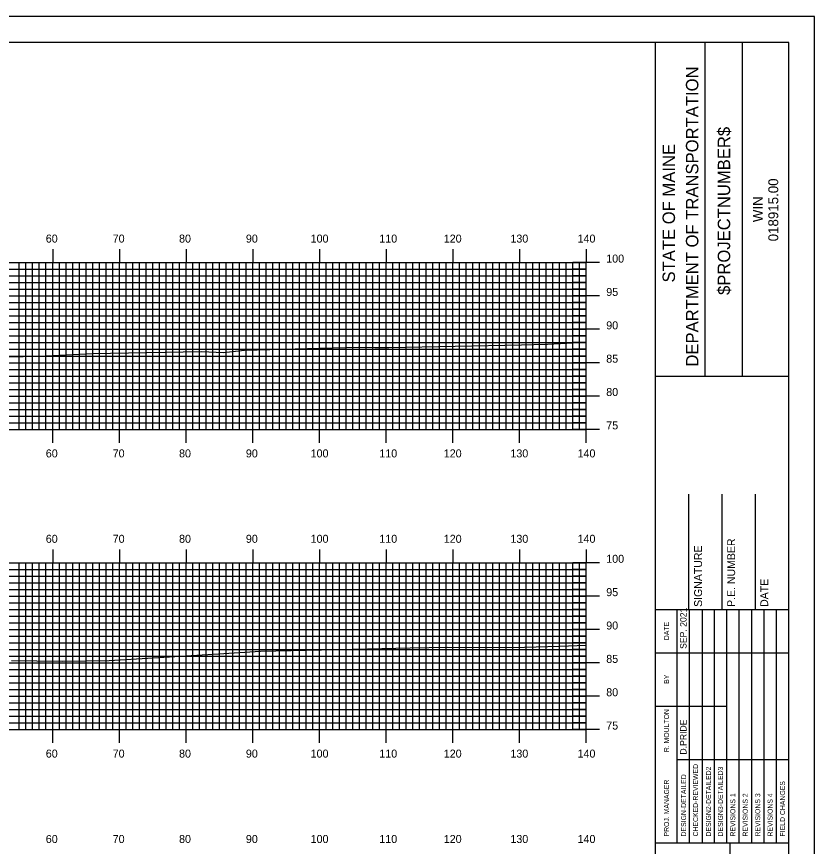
# Model space of a CAD drawing. Extents: x 1777531 to 1777875, y 442591 to 442811.
# Drawn here: x 1777751.9 to 1777871.5, y 442686.2 to 442810.5 of the extents above; entities that cross this region are included whole.
import ezdxf

# ---------------------------------------------------------------- set-up
doc = ezdxf.new("R2010")
doc.units = 0
for name, color, linetype in [('BORDER', 7, 'Continuous'), ('H_V ANNOTATION', 7, 'Continuous'), ('MAJOR', 7, 'Continuous'), ('MINOR', 7, 'Continuous'), ('PLOT BOUNDARY', 7, 'Continuous'), ('S_Roadway_Centerline', 7, 'Continuous')]:
    doc.layers.add(name, color=color, linetype=linetype)

msp = doc.modelspace()

# ---------------------------------------------------------------- linework, layer by layer
at = {"layer": 'BORDER'}
for p, q in [((1777847.68, 442596.67), (1777847.68, 442806.67)), ((1777855.13, 442756.66), (1777855.13, 442806.66)), ((1777860.72, 442756.66), (1777860.72, 442806.66)), ((1777847.68, 442756.65), (1777867.68, 442756.65)), ((1777852.68, 442721.67), (1777852.68, 442738.97)), ((1777857.68, 442721.67), (1777857.68, 442738.97)), ((1777862.68, 442721.67), (1777862.68, 442738.97)), ((1777847.68, 442721.67), (1777867.68, 442721.67)), ((1777847.68, 442686.67), (1777867.68, 442686.67)), ((1777858.86, 442616.67), (1777858.86, 442686.67))]:
    msp.add_line(p, q, dxfattribs=at)
msp.add_lwpolyline([(1777547.68, 442596.67), (1777867.68, 442596.67), (1777867.68, 442806.67), (1777547.68, 442806.67)], close=True, dxfattribs=at)
for points in [[(1777850.91, 442715.17), (1777850.91, 442721.67)], [(1777852.77, 442686.68), (1777852.77, 442721.67)], [(1777854.64, 442721.67), (1777854.64, 442686.68)], [(1777856.5, 442686.68), (1777856.5, 442721.67)], [(1777858.36, 442686.68), (1777858.36, 442721.67)], [(1777860.23, 442686.68), (1777860.23, 442721.67)], [(1777862.09, 442686.68), (1777862.09, 442721.67)], [(1777863.95, 442686.68), (1777863.95, 442721.67)], [(1777865.82, 442686.68), (1777865.82, 442721.67)], [(1777850.91, 442686.68), (1777850.91, 442720.26)], [(1777847.68, 442715.17), (1777867.68, 442715.17)], [(1777847.68, 442707.17), (1777850.91, 442707.17)], [(1777850.91, 442707.17), (1777858.36, 442707.17)], [(1777850.91, 442699.17), (1777867.68, 442699.17)]]:
    msp.add_lwpolyline(points, dxfattribs=at)
at = {"layer": 'MAJOR'}
for p, q in [((1777757.28, 442775.67), (1777757.28, 442773.67)), ((1777767.28, 442775.67), (1777767.28, 442773.67)), ((1777777.28, 442775.67), (1777777.28, 442773.67)), ((1777787.28, 442775.67), (1777787.28, 442773.67)), ((1777797.28, 442775.67), (1777797.28, 442773.67)), ((1777807.28, 442775.67), (1777807.28, 442773.67)), ((1777817.28, 442775.67), (1777817.28, 442773.67)), ((1777827.28, 442775.67), (1777827.28, 442773.67)), ((1777837.28, 442775.67), (1777837.28, 442773.67)), ((1777557.28, 442773.67), (1777837.28, 442773.67)), ((1777557.28, 442773.67), (1777837.28, 442773.67)), ((1777757.28, 442748.67), (1777757.28, 442773.67)), ((1777767.28, 442748.67), (1777767.28, 442773.67)), ((1777777.28, 442748.67), (1777777.28, 442773.67)), ((1777787.28, 442748.67), (1777787.28, 442773.67)), ((1777797.28, 442748.67), (1777797.28, 442773.67)), ((1777807.28, 442748.67), (1777807.28, 442773.67)), ((1777817.28, 442748.67), (1777817.28, 442773.67)), ((1777827.28, 442748.67), (1777827.28, 442773.67)), ((1777839.28, 442773.67), (1777835.27, 442773.67)), ((1777837.28, 442748.67), (1777837.28, 442773.67)), ((1777837.28, 442748.67), (1777837.28, 442773.67)), ((1777557.28, 442768.67), (1777837.28, 442768.67)), ((1777839.28, 442768.67), (1777835.27, 442768.67)), ((1777557.28, 442763.67), (1777837.28, 442763.67)), ((1777839.28, 442763.67), (1777835.27, 442763.67)), ((1777557.28, 442758.67), (1777837.28, 442758.67)), ((1777839.28, 442758.67), (1777835.27, 442758.67)), ((1777557.28, 442753.67), (1777837.28, 442753.67)), ((1777839.28, 442753.67), (1777835.27, 442753.67)), ((1777557.28, 442748.67), (1777837.28, 442748.67)), ((1777557.28, 442748.67), (1777837.28, 442748.67)), ((1777757.28, 442746.66), (1777757.28, 442748.67)), ((1777767.28, 442746.66), (1777767.28, 442748.67)), ((1777777.28, 442746.66), (1777777.28, 442748.67)), ((1777787.28, 442746.66), (1777787.28, 442748.67)), ((1777797.28, 442746.66), (1777797.28, 442748.67)), ((1777807.28, 442746.66), (1777807.28, 442748.67)), ((1777817.28, 442746.66), (1777817.28, 442748.67)), ((1777827.28, 442746.66), (1777827.28, 442748.67)), ((1777839.28, 442748.67), (1777835.27, 442748.67)), ((1777837.28, 442746.66), (1777837.28, 442748.67)), ((1777757.28, 442730.67), (1777757.28, 442728.67)), ((1777767.28, 442730.67), (1777767.28, 442728.67)), ((1777777.28, 442730.67), (1777777.28, 442728.67)), ((1777787.28, 442730.67), (1777787.28, 442728.67)), ((1777797.28, 442730.67), (1777797.28, 442728.67)), ((1777807.28, 442730.67), (1777807.28, 442728.67)), ((1777817.28, 442730.67), (1777817.28, 442728.67)), ((1777827.28, 442730.67), (1777827.28, 442728.67)), ((1777837.28, 442730.67), (1777837.28, 442728.67)), ((1777557.28, 442728.67), (1777837.28, 442728.67)), ((1777557.28, 442728.67), (1777837.28, 442728.67)), ((1777757.28, 442703.67), (1777757.28, 442728.67)), ((1777767.28, 442703.67), (1777767.28, 442728.67)), ((1777777.28, 442703.67), (1777777.28, 442728.67)), ((1777787.28, 442703.67), (1777787.28, 442728.67)), ((1777797.28, 442703.67), (1777797.28, 442728.67)), ((1777807.28, 442703.67), (1777807.28, 442728.67)), ((1777817.28, 442703.67), (1777817.28, 442728.67)), ((1777827.28, 442703.67), (1777827.28, 442728.67)), ((1777839.28, 442728.67), (1777835.27, 442728.67)), ((1777837.28, 442703.67), (1777837.28, 442728.67)), ((1777837.28, 442703.67), (1777837.28, 442728.67)), ((1777557.28, 442723.67), (1777837.28, 442723.67)), ((1777839.28, 442723.67), (1777835.27, 442723.67)), ((1777557.28, 442718.67), (1777837.28, 442718.67)), ((1777839.28, 442718.67), (1777835.27, 442718.67)), ((1777557.28, 442713.67), (1777837.28, 442713.67)), ((1777839.28, 442713.67), (1777835.27, 442713.67)), ((1777557.28, 442708.67), (1777837.28, 442708.67)), ((1777839.28, 442708.67), (1777835.27, 442708.67)), ((1777557.28, 442703.67), (1777837.28, 442703.67)), ((1777557.28, 442703.67), (1777837.28, 442703.67)), ((1777757.28, 442701.66), (1777757.28, 442703.67)), ((1777767.28, 442701.66), (1777767.28, 442703.67)), ((1777777.28, 442701.66), (1777777.28, 442703.67)), ((1777787.28, 442701.66), (1777787.28, 442703.67)), ((1777797.28, 442701.66), (1777797.28, 442703.67)), ((1777807.28, 442701.66), (1777807.28, 442703.67)), ((1777817.28, 442701.66), (1777817.28, 442703.67)), ((1777827.28, 442701.66), (1777827.28, 442703.67)), ((1777839.28, 442703.67), (1777835.27, 442703.67)), ((1777837.28, 442701.66), (1777837.28, 442703.67))]:
    msp.add_line(p, q, dxfattribs=at)
at = {"layer": 'MINOR'}
for p, q in [((1777752.28, 442748.67), (1777752.28, 442773.67)), ((1777753.28, 442748.67), (1777753.28, 442773.67)), ((1777754.28, 442748.67), (1777754.28, 442773.67)), ((1777755.28, 442748.67), (1777755.28, 442773.67)), ((1777756.28, 442748.67), (1777756.28, 442773.67)), ((1777758.28, 442748.67), (1777758.28, 442773.67)), ((1777759.28, 442748.67), (1777759.28, 442773.67)), ((1777760.28, 442748.67), (1777760.28, 442773.67)), ((1777761.28, 442748.67), (1777761.28, 442773.67)), ((1777762.28, 442748.67), (1777762.28, 442773.67)), ((1777763.28, 442748.67), (1777763.28, 442773.67)), ((1777764.28, 442748.67), (1777764.28, 442773.67)), ((1777765.28, 442748.67), (1777765.28, 442773.67)), ((1777766.28, 442748.67), (1777766.28, 442773.67)), ((1777768.28, 442748.67), (1777768.28, 442773.67)), ((1777769.28, 442748.67), (1777769.28, 442773.67)), ((1777770.28, 442748.67), (1777770.28, 442773.67)), ((1777771.28, 442748.67), (1777771.28, 442773.67)), ((1777772.28, 442748.67), (1777772.28, 442773.67)), ((1777773.28, 442748.67), (1777773.28, 442773.67)), ((1777774.28, 442748.67), (1777774.28, 442773.67)), ((1777775.28, 442748.67), (1777775.28, 442773.67)), ((1777776.28, 442748.67), (1777776.28, 442773.67)), ((1777778.28, 442748.67), (1777778.28, 442773.67)), ((1777779.28, 442748.67), (1777779.28, 442773.67)), ((1777780.28, 442748.67), (1777780.28, 442773.67)), ((1777781.28, 442748.67), (1777781.28, 442773.67)), ((1777782.28, 442748.67), (1777782.28, 442773.67)), ((1777783.28, 442748.67), (1777783.28, 442773.67)), ((1777784.28, 442748.67), (1777784.28, 442773.67)), ((1777785.28, 442748.67), (1777785.28, 442773.67)), ((1777786.28, 442748.67), (1777786.28, 442773.67)), ((1777788.28, 442748.67), (1777788.28, 442773.67)), ((1777789.28, 442748.67), (1777789.28, 442773.67)), ((1777790.28, 442748.67), (1777790.28, 442773.67)), ((1777791.28, 442748.67), (1777791.28, 442773.67)), ((1777792.28, 442748.67), (1777792.28, 442773.67)), ((1777793.28, 442748.67), (1777793.28, 442773.67)), ((1777794.28, 442748.67), (1777794.28, 442773.67)), ((1777795.28, 442748.67), (1777795.28, 442773.67)), ((1777796.28, 442748.67), (1777796.28, 442773.67)), ((1777798.28, 442748.67), (1777798.28, 442773.67)), ((1777799.28, 442748.67), (1777799.28, 442773.67)), ((1777800.28, 442748.67), (1777800.28, 442773.67)), ((1777801.28, 442748.67), (1777801.28, 442773.67)), ((1777802.28, 442748.67), (1777802.28, 442773.67)), ((1777803.28, 442748.67), (1777803.28, 442773.67)), ((1777804.28, 442748.67), (1777804.28, 442773.67)), ((1777805.28, 442748.67), (1777805.28, 442773.67)), ((1777806.28, 442748.67), (1777806.28, 442773.67)), ((1777808.28, 442748.67), (1777808.28, 442773.67)), ((1777809.28, 442748.67), (1777809.28, 442773.67)), ((1777810.28, 442748.67), (1777810.28, 442773.67)), ((1777811.28, 442748.67), (1777811.28, 442773.67)), ((1777812.28, 442748.67), (1777812.28, 442773.67)), ((1777813.28, 442748.67), (1777813.28, 442773.67)), ((1777814.28, 442748.67), (1777814.28, 442773.67)), ((1777815.28, 442748.67), (1777815.28, 442773.67)), ((1777816.28, 442748.67), (1777816.28, 442773.67)), ((1777818.28, 442748.67), (1777818.28, 442773.67)), ((1777819.28, 442748.67), (1777819.28, 442773.67)), ((1777820.28, 442748.67), (1777820.28, 442773.67)), ((1777821.28, 442748.67), (1777821.28, 442773.67)), ((1777822.28, 442748.67), (1777822.28, 442773.67)), ((1777823.28, 442748.67), (1777823.28, 442773.67)), ((1777824.28, 442748.67), (1777824.28, 442773.67)), ((1777825.28, 442748.67), (1777825.28, 442773.67)), ((1777826.28, 442748.67), (1777826.28, 442773.67)), ((1777828.28, 442748.67), (1777828.28, 442773.67)), ((1777829.28, 442748.67), (1777829.28, 442773.67)), ((1777830.28, 442748.67), (1777830.28, 442773.67)), ((1777831.28, 442748.67), (1777831.28, 442773.67)), ((1777832.28, 442748.67), (1777832.28, 442773.67)), ((1777833.28, 442748.67), (1777833.28, 442773.67)), ((1777834.28, 442748.67), (1777834.28, 442773.67)), ((1777835.28, 442748.67), (1777835.28, 442773.67)), ((1777836.28, 442748.67), (1777836.28, 442773.67)), ((1777557.28, 442772.67), (1777837.28, 442772.67)), ((1777837.28, 442772.67), (1777835.27, 442772.67)), ((1777557.28, 442771.67), (1777837.28, 442771.67)), ((1777837.28, 442771.67), (1777835.27, 442771.67)), ((1777557.28, 442770.67), (1777837.28, 442770.67)), ((1777837.28, 442770.67), (1777835.27, 442770.67)), ((1777557.28, 442769.67), (1777837.28, 442769.67)), ((1777837.28, 442769.67), (1777835.27, 442769.67)), ((1777557.28, 442767.67), (1777837.28, 442767.67)), ((1777837.28, 442767.67), (1777835.27, 442767.67)), ((1777557.28, 442766.67), (1777837.28, 442766.67)), ((1777837.28, 442766.67), (1777835.27, 442766.67)), ((1777557.28, 442765.67), (1777837.28, 442765.67)), ((1777837.28, 442765.67), (1777835.27, 442765.67)), ((1777557.28, 442764.67), (1777837.28, 442764.67)), ((1777837.28, 442764.67), (1777835.27, 442764.67)), ((1777557.28, 442762.67), (1777837.28, 442762.67)), ((1777837.28, 442762.67), (1777835.27, 442762.67)), ((1777557.28, 442761.67), (1777837.28, 442761.67)), ((1777837.28, 442761.67), (1777835.27, 442761.67)), ((1777557.28, 442760.67), (1777837.28, 442760.67)), ((1777837.28, 442760.67), (1777835.27, 442760.67)), ((1777557.28, 442759.67), (1777837.28, 442759.67)), ((1777837.28, 442759.67), (1777835.27, 442759.67)), ((1777557.28, 442757.67), (1777837.28, 442757.67)), ((1777837.28, 442757.67), (1777835.27, 442757.67)), ((1777557.28, 442756.67), (1777837.28, 442756.67)), ((1777837.28, 442756.67), (1777835.27, 442756.67)), ((1777557.28, 442755.67), (1777837.28, 442755.67)), ((1777837.28, 442755.67), (1777835.27, 442755.67)), ((1777557.28, 442754.67), (1777837.28, 442754.67)), ((1777837.28, 442754.67), (1777835.27, 442754.67)), ((1777557.28, 442752.67), (1777837.28, 442752.67)), ((1777837.28, 442752.67), (1777835.27, 442752.67)), ((1777557.28, 442751.67), (1777837.28, 442751.67)), ((1777837.28, 442751.67), (1777835.27, 442751.67)), ((1777557.28, 442750.67), (1777837.28, 442750.67)), ((1777837.28, 442750.67), (1777835.27, 442750.67)), ((1777557.28, 442749.67), (1777837.28, 442749.67)), ((1777837.28, 442749.67), (1777835.27, 442749.67)), ((1777557.28, 442727.67), (1777837.28, 442727.67)), ((1777752.28, 442703.67), (1777752.28, 442728.67)), ((1777753.28, 442703.67), (1777753.28, 442728.67)), ((1777754.28, 442703.67), (1777754.28, 442728.67)), ((1777755.28, 442703.67), (1777755.28, 442728.67)), ((1777756.28, 442703.67), (1777756.28, 442728.67)), ((1777758.28, 442703.67), (1777758.28, 442728.67)), ((1777759.28, 442703.67), (1777759.28, 442728.67)), ((1777760.28, 442703.67), (1777760.28, 442728.67)), ((1777761.28, 442703.67), (1777761.28, 442728.67)), ((1777762.28, 442703.67), (1777762.28, 442728.67)), ((1777763.28, 442703.67), (1777763.28, 442728.67)), ((1777764.28, 442703.67), (1777764.28, 442728.67)), ((1777765.28, 442703.67), (1777765.28, 442728.67)), ((1777766.28, 442703.67), (1777766.28, 442728.67)), ((1777768.28, 442703.67), (1777768.28, 442728.67)), ((1777769.28, 442703.67), (1777769.28, 442728.67)), ((1777770.28, 442703.67), (1777770.28, 442728.67)), ((1777771.28, 442703.67), (1777771.28, 442728.67)), ((1777772.28, 442703.67), (1777772.28, 442728.67)), ((1777773.28, 442703.67), (1777773.28, 442728.67)), ((1777774.28, 442703.67), (1777774.28, 442728.67)), ((1777775.28, 442703.67), (1777775.28, 442728.67)), ((1777776.28, 442703.67), (1777776.28, 442728.67)), ((1777778.28, 442703.67), (1777778.28, 442728.67)), ((1777779.28, 442703.67), (1777779.28, 442728.67)), ((1777780.28, 442703.67), (1777780.28, 442728.67)), ((1777781.28, 442703.67), (1777781.28, 442728.67)), ((1777782.28, 442703.67), (1777782.28, 442728.67)), ((1777783.28, 442703.67), (1777783.28, 442728.67)), ((1777784.28, 442703.67), (1777784.28, 442728.67)), ((1777785.28, 442703.67), (1777785.28, 442728.67)), ((1777786.28, 442703.67), (1777786.28, 442728.67)), ((1777788.28, 442703.67), (1777788.28, 442728.67)), ((1777789.28, 442703.67), (1777789.28, 442728.67)), ((1777790.28, 442703.67), (1777790.28, 442728.67)), ((1777791.28, 442703.67), (1777791.28, 442728.67)), ((1777792.28, 442703.67), (1777792.28, 442728.67)), ((1777793.28, 442703.67), (1777793.28, 442728.67)), ((1777794.28, 442703.67), (1777794.28, 442728.67)), ((1777795.28, 442703.67), (1777795.28, 442728.67)), ((1777796.28, 442703.67), (1777796.28, 442728.67)), ((1777798.28, 442703.67), (1777798.28, 442728.67)), ((1777799.28, 442703.67), (1777799.28, 442728.67)), ((1777800.28, 442703.67), (1777800.28, 442728.67)), ((1777801.28, 442703.67), (1777801.28, 442728.67)), ((1777802.28, 442703.67), (1777802.28, 442728.67)), ((1777803.28, 442703.67), (1777803.28, 442728.67)), ((1777804.28, 442703.67), (1777804.28, 442728.67)), ((1777805.28, 442703.67), (1777805.28, 442728.67)), ((1777806.28, 442703.67), (1777806.28, 442728.67)), ((1777808.28, 442703.67), (1777808.28, 442728.67)), ((1777809.28, 442703.67), (1777809.28, 442728.67)), ((1777810.28, 442703.67), (1777810.28, 442728.67)), ((1777811.28, 442703.67), (1777811.28, 442728.67)), ((1777812.28, 442703.67), (1777812.28, 442728.67)), ((1777813.28, 442703.67), (1777813.28, 442728.67)), ((1777814.28, 442703.67), (1777814.28, 442728.67)), ((1777815.28, 442703.67), (1777815.28, 442728.67)), ((1777816.28, 442703.67), (1777816.28, 442728.67)), ((1777818.28, 442703.67), (1777818.28, 442728.67)), ((1777819.28, 442703.67), (1777819.28, 442728.67)), ((1777820.28, 442703.67), (1777820.28, 442728.67)), ((1777821.28, 442703.67), (1777821.28, 442728.67)), ((1777822.28, 442703.67), (1777822.28, 442728.67)), ((1777823.28, 442703.67), (1777823.28, 442728.67)), ((1777824.28, 442703.67), (1777824.28, 442728.67)), ((1777825.28, 442703.67), (1777825.28, 442728.67)), ((1777826.28, 442703.67), (1777826.28, 442728.67)), ((1777828.28, 442703.67), (1777828.28, 442728.67)), ((1777829.28, 442703.67), (1777829.28, 442728.67)), ((1777830.28, 442703.67), (1777830.28, 442728.67)), ((1777831.28, 442703.67), (1777831.28, 442728.67)), ((1777832.28, 442703.67), (1777832.28, 442728.67)), ((1777833.28, 442703.67), (1777833.28, 442728.67)), ((1777834.28, 442703.67), (1777834.28, 442728.67)), ((1777837.28, 442727.67), (1777835.27, 442727.67)), ((1777835.28, 442703.67), (1777835.28, 442728.67)), ((1777836.28, 442703.67), (1777836.28, 442728.67)), ((1777557.28, 442726.67), (1777837.28, 442726.67)), ((1777837.28, 442726.67), (1777835.27, 442726.67)), ((1777557.28, 442725.67), (1777837.28, 442725.67)), ((1777837.28, 442725.67), (1777835.27, 442725.67)), ((1777557.28, 442724.67), (1777837.28, 442724.67)), ((1777837.28, 442724.67), (1777835.27, 442724.67)), ((1777557.28, 442722.67), (1777837.28, 442722.67)), ((1777837.28, 442722.67), (1777835.27, 442722.67)), ((1777557.28, 442721.67), (1777837.28, 442721.67)), ((1777837.28, 442721.67), (1777835.27, 442721.67)), ((1777557.28, 442720.67), (1777837.28, 442720.67)), ((1777837.28, 442720.67), (1777835.27, 442720.67)), ((1777557.28, 442719.67), (1777837.28, 442719.67)), ((1777837.28, 442719.67), (1777835.27, 442719.67)), ((1777557.28, 442717.67), (1777837.28, 442717.67)), ((1777837.28, 442717.67), (1777835.27, 442717.67)), ((1777557.28, 442716.67), (1777837.28, 442716.67)), ((1777837.28, 442716.67), (1777835.27, 442716.67)), ((1777557.28, 442715.67), (1777837.28, 442715.67)), ((1777837.28, 442715.67), (1777835.27, 442715.67)), ((1777557.28, 442714.67), (1777837.28, 442714.67)), ((1777837.28, 442714.67), (1777835.27, 442714.67)), ((1777557.28, 442712.67), (1777837.28, 442712.67)), ((1777837.28, 442712.67), (1777835.27, 442712.67)), ((1777557.28, 442711.67), (1777837.28, 442711.67)), ((1777837.28, 442711.67), (1777835.27, 442711.67)), ((1777557.28, 442710.67), (1777837.28, 442710.67)), ((1777837.28, 442710.67), (1777835.27, 442710.67)), ((1777557.28, 442709.67), (1777837.28, 442709.67)), ((1777837.28, 442709.67), (1777835.27, 442709.67)), ((1777557.28, 442707.67), (1777837.28, 442707.67)), ((1777557.28, 442706.67), (1777837.28, 442706.67)), ((1777837.28, 442707.67), (1777835.27, 442707.67)), ((1777837.28, 442706.67), (1777835.27, 442706.67)), ((1777557.28, 442705.67), (1777837.28, 442705.67)), ((1777837.28, 442705.67), (1777835.27, 442705.67)), ((1777557.28, 442704.67), (1777837.28, 442704.67)), ((1777837.28, 442704.67), (1777835.27, 442704.67))]:
    msp.add_line(p, q, dxfattribs=at)
at = {"layer": 'PLOT BOUNDARY'}
msp.add_lwpolyline([(1777531.49, 442590.55), (1777871.49, 442590.55), (1777871.49, 442810.55), (1777531.49, 442810.55)], close=True, dxfattribs=at)
at = {"layer": 'S_Roadway_Centerline'}
for points in [[(1777747.89, 442759.49), (1777755.31, 442759.67), (1777763.22, 442760.05), (1777779.57, 442760.32), (1777782.88, 442760.21), (1777786.04, 442760.55), (1777803.1, 442760.98), (1777805.59, 442760.92), (1777807.67, 442760.95), (1777827.59, 442761.34), (1777829.4, 442761.39), (1777831.49, 442761.46), (1777837.28, 442761.73)], [(1777751.12, 442714.04), (1777758.7, 442713.92), (1777765.74, 442714.04), (1777781.33, 442715), (1777788.44, 442715.43), (1777804.48, 442715.79), (1777810.86, 442715.92), (1777816.54, 442716), (1777822.45, 442715.99), (1777828, 442716.02), (1777833.29, 442716.17), (1777837.28, 442716.34)]]:
    msp.add_lwpolyline(points, dxfattribs=at)

# ---------------------------------------------------------------- texts
at = {"layer": 'BORDER'}
for s, height, p in [('DEPARTMENT OF TRANSPORTATION', 1.8635, (1777854.09, 442758.08)), ('$PROJECTNUMBER$', 1.8635, (1777858.86, 442768.82)), ('STATE OF MAINE', 1.8635, (1777850.59, 442770.69)), ('018915.00', 1.491, (1777866.07, 442776.86)), ('WIN', 1.491, (1777863.75, 442779.73)), ('P.E. NUMBER', 1.1811, (1777859.6, 442722.06)), ('SIGNATURE', 1.181, (1777854.64, 442722.06)), ('DATE', 1.181, (1777864.56, 442722.06)), ('SEP. 2021', 0.969, (1777852.32, 442715.76)), ('DATE', 0.743, (1777849.69, 442717.08)), ('BY', 0.743, (1777849.69, 442710.54)), ('R. MOULTON', 0.745, (1777849.69, 442700.28)), ('D.PRIDE', 0.969, (1777852.32, 442699.92)), ('CHECKED-REVIEWED', 0.7455, (1777854.04, 442687.65)), ('DESIGN2-DETAILED2', 0.7455, (1777855.98, 442687.65)), ('DESIGN3-DETAILED3', 0.7455, (1777857.77, 442687.65)), ('DESIGN-DETAILED', 0.7455, (1777852.25, 442687.65)), ('PROJ. MANAGER', 0.7455, (1777849.69, 442687.65)), ('FIELD CHANGES', 0.7455, (1777867.08, 442687.65)), ('REVISIONS 1', 0.7455, (1777859.63, 442687.65)), ('REVISIONS 2', 0.7455, (1777861.49, 442687.65)), ('REVISIONS 3', 0.7455, (1777863.36, 442687.65)), ('REVISIONS 4', 0.7455, (1777865.22, 442687.65))]:
    msp.add_text(s, height=height, rotation=90, dxfattribs=at).set_placement(p)
at = {"layer": 'H_V ANNOTATION'}
for s, p in [('60', (1777756.25, 442776.67)), ('70', (1777766.28, 442776.67)), ('80', (1777776.23, 442776.67)), ('90', (1777786.25, 442776.67)), ('100', (1777795.96, 442776.67)), ('110', (1777806.26, 442776.67)), ('120', (1777815.92, 442776.67)), ('130', (1777825.91, 442776.67)), ('140', (1777835.98, 442776.67)), ('100', (1777840.28, 442773.67)), ('95', (1777840.28, 442768.67)), ('90', (1777840.28, 442763.67)), ('85', (1777840.28, 442758.67)), ('80', (1777840.28, 442753.67)), ('75', (1777840.28, 442748.67)), ('60', (1777756.25, 442744.47)), ('70', (1777766.28, 442744.47)), ('80', (1777776.23, 442744.47)), ('90', (1777786.25, 442744.47)), ('100', (1777795.96, 442744.47)), ('110', (1777806.26, 442744.47)), ('120', (1777815.92, 442744.47)), ('130', (1777825.91, 442744.47)), ('140', (1777835.98, 442744.47)), ('60', (1777756.25, 442731.67)), ('70', (1777766.28, 442731.67)), ('80', (1777776.23, 442731.67)), ('90', (1777786.25, 442731.67)), ('100', (1777795.96, 442731.67)), ('110', (1777806.26, 442731.67)), ('120', (1777815.92, 442731.67)), ('130', (1777825.91, 442731.67)), ('140', (1777835.98, 442731.67)), ('100', (1777840.28, 442728.67)), ('95', (1777840.28, 442723.67)), ('90', (1777840.28, 442718.67)), ('85', (1777840.28, 442713.67)), ('80', (1777840.28, 442708.67)), ('75', (1777840.28, 442703.67)), ('60', (1777756.25, 442699.47)), ('70', (1777766.28, 442699.47)), ('80', (1777776.23, 442699.47)), ('90', (1777786.25, 442699.47)), ('100', (1777795.96, 442699.47)), ('110', (1777806.26, 442699.47)), ('120', (1777815.92, 442699.47)), ('130', (1777825.91, 442699.47)), ('140', (1777835.98, 442699.47)), ('60', (1777756.25, 442686.67)), ('70', (1777766.28, 442686.67)), ('80', (1777776.23, 442686.67)), ('90', (1777786.25, 442686.67)), ('100', (1777795.96, 442686.67)), ('110', (1777806.26, 442686.67)), ('120', (1777815.92, 442686.67)), ('130', (1777825.91, 442686.67)), ('140', (1777835.98, 442686.67))]:
    msp.add_text(s, height=1.2, dxfattribs=at).set_placement(p)

doc.saveas('drawing.dxf')
